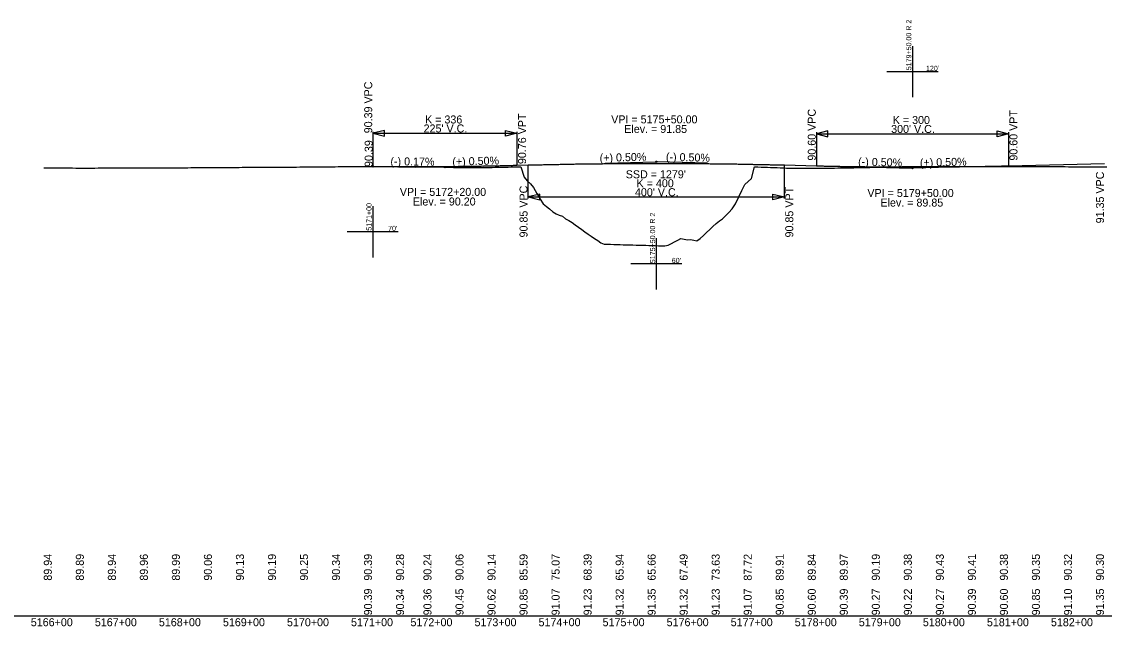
# Model space of a CAD drawing. Extents: x 2147288 to 2220488, y 740833 to 759333.
# Drawn here: x 2148940 to 2150631, y 758067 to 759012 of the extents above; entities that cross this region are included whole.
import ezdxf

# ---------------------------------------------------------------- set-up
doc = ezdxf.new("R2010")
doc.units = 0
for name, color, linetype in [('RD_DDB_GradeTX', 7, 'Continuous'), ('RD_DDB_Profile_EX', 7, 'Continuous'), ('RD_DDB_Profile_Lbl', 7, 'Continuous'), ('RD_DDB_Profile_PR', 7, 'Continuous'), ('RD_DDB_StaTX', 7, 'Continuous'), ('RD_DDB_StripGrade', 7, 'Continuous'), ('RD_DDB_VCLbl', 7, 'Continuous'), ('RD_GPK_Profile_Cell', 7, 'Continuous')]:
    doc.layers.add(name, color=color, linetype=linetype)

msp = doc.modelspace()

# ---------------------------------------------------------------- linework, layer by layer
at = {"layer": 'RD_DDB_GradeTX'}
for p, q in [((2149851.1, 758790.7), (2149930.1, 758792.7)), ((2150011.1, 758790.7), (2149932.1, 758792.7)), ((2149538.3, 758785), (2149600.1, 758784.4)), ((2149681.1, 758786.4), (2149602.1, 758784.5)), ((2150251.1, 758784.7), (2150330.1, 758782.7)), ((2150411.1, 758784.7), (2150332.1, 758782.7))]:
    msp.add_line(p, q, dxfattribs=at)
for centre in [(2149931.1, 758792.7), (2149488.3, 758785.4), (2149601.1, 758784.4), (2150331.1, 758782.7)]:
    msp.add_circle(centre, 1, dxfattribs=at)
at = {"layer": 'RD_DDB_Profile_EX'}
for points in [[(2148974.6, 758783.1), (2148979.6, 758783.1), (2148984.6, 758783.1), (2148989.6, 758783.1), (2148994.6, 758783.2), (2148999.6, 758783.1), (2149004.6, 758783.1), (2149009.6, 758783), (2149014.6, 758783), (2149019.6, 758783), (2149024.6, 758782.9), (2149029.6, 758782.9), (2149034.6, 758782.8), (2149039.6, 758782.9), (2149044.6, 758782.9), (2149049.6, 758782.9), (2149054.6, 758782.9), (2149059.6, 758783), (2149064.6, 758783), (2149069.6, 758783), (2149074.6, 758783), (2149079.6, 758783.1), (2149084.6, 758783.1), (2149089.6, 758783.1), (2149094.6, 758783.2), (2149099.6, 758783.2), (2149104.6, 758783.2), (2149109.6, 758783.2), (2149114.6, 758783.2), (2149119.6, 758783.2), (2149124.6, 758783.2), (2149129.6, 758783.2), (2149134.6, 758783.2), (2149139.6, 758783.2), (2149144.6, 758783.2), (2149149.6, 758783.2), (2149154.6, 758783.2), (2149159.6, 758783.3), (2149164.6, 758783.3), (2149169.6, 758783.3), (2149174.6, 758783.3), (2149179.6, 758783.3), (2149184.6, 758783.3), (2149189.6, 758783.4), (2149194.6, 758783.4), (2149199.6, 758783.4), (2149204.6, 758783.5), (2149209.6, 758783.5), (2149214.6, 758783.5), (2149219.6, 758783.6), (2149224.6, 758783.6), (2149229.6, 758783.6), (2149234.6, 758783.7), (2149239.6, 758783.7), (2149244.6, 758783.8), (2149249.6, 758783.8), (2149254.6, 758783.8), (2149259.6, 758783.9), (2149264.6, 758783.9), (2149269.6, 758784), (2149274.6, 758784), (2149279.6, 758784), (2149284.6, 758784.1), (2149289.6, 758784.1), (2149294.6, 758784.1), (2149299.6, 758784.2), (2149304.6, 758784.2), (2149309.6, 758784.2), (2149314.6, 758784.2), (2149319.6, 758784.3), (2149324.6, 758784.3), (2149329.6, 758784.3), (2149334.6, 758784.3), (2149339.6, 758784.4), (2149344.6, 758784.4), (2149349.6, 758784.4), (2149354.6, 758784.4), (2149359.6, 758784.5), (2149364.6, 758784.5), (2149369.6, 758784.5), (2149374.6, 758784.6), (2149379.6, 758784.6), (2149384.6, 758784.7), (2149389.6, 758784.7), (2149394.6, 758784.7), (2149399.6, 758784.8), (2149404.6, 758784.8), (2149409.6, 758784.9), (2149414.6, 758784.9), (2149419.6, 758784.9), (2149424.6, 758785), (2149429.6, 758785), (2149434.6, 758785.1), (2149439.6, 758785.1), (2149444.6, 758785.2), (2149449.6, 758785.2), (2149454.6, 758785.3), (2149459.6, 758785.3), (2149464.6, 758785.4), (2149469.6, 758785.4), (2149474.6, 758785.5)], [(2149474.6, 758785.5), (2149479.6, 758785.4), (2149484.6, 758785.4), (2149489.6, 758785.4), (2149494.6, 758785.4), (2149499.6, 758785.3), (2149504.6, 758785.3), (2149509.6, 758785.3), (2149514.6, 758785.2), (2149519.6, 758785.1), (2149524.6, 758785.1), (2149529.6, 758785), (2149534.6, 758784.9), (2149538.3, 758784.8)], [(2149538.3, 758784.8), (2149539.6, 758784.8), (2149544.6, 758784.7), (2149549.6, 758784.6), (2149554.6, 758784.5), (2149559.6, 758784.6), (2149564.6, 758784.6), (2149569.6, 758784.6), (2149574.6, 758784.6), (2149579.6, 758784.6), (2149584.6, 758784.6), (2149589.6, 758784.7), (2149594.6, 758784.6), (2149599.6, 758784.4), (2149604.6, 758784.3), (2149609.6, 758784.1), (2149614.6, 758784), (2149619.6, 758783.8), (2149624.6, 758783.8), (2149629.6, 758783.7), (2149634.6, 758783.7), (2149639.6, 758783.7), (2149644.6, 758783.7), (2149649.6, 758783.8), (2149654.6, 758783.8), (2149659.6, 758783.9), (2149664.6, 758783.9), (2149669.6, 758784), (2149674.6, 758784), (2149679.6, 758784.1), (2149684.6, 758784.2), (2149689.6, 758784.3), (2149694.6, 758784.4), (2149699.6, 758784.5), (2149704.6, 758784.6), (2149709.6, 758784.7), (2149714.6, 758784.8), (2149719.6, 758784.8), (2149724.6, 758768.8), (2149729.6, 758762.7), (2149734.6, 758758.3), (2149739.6, 758752.4), (2149744.6, 758742.9), (2149749.6, 758734.1), (2149754.6, 758727.2), (2149759.6, 758723.1), (2149764.6, 758719), (2149769.6, 758714.6), (2149774.6, 758711.4), (2149779.6, 758709.2), (2149784.6, 758707.6), (2149789.6, 758703.4), (2149794.6, 758701), (2149799.6, 758697.7), (2149804.6, 758694.3), (2149809.6, 758690.6), (2149814.6, 758686.9), (2149819.6, 758683.3), (2149824.6, 758679.8), (2149829.6, 758676.4), (2149834.6, 758673), (2149839.6, 758669.6), (2149844.6, 758666.2), (2149849.6, 758664), (2149854.6, 758663.9), (2149859.6, 758663.8), (2149864.6, 758663.6), (2149869.6, 758663.5), (2149874.6, 758663.3), (2149879.6, 758663.2), (2149884.6, 758663), (2149889.6, 758662.9), (2149894.6, 758662.8), (2149899.6, 758662.6), (2149904.6, 758662.5), (2149909.6, 758662.3), (2149914.6, 758662.2), (2149919.6, 758662.1), (2149924.6, 758661.9), (2149929.6, 758661.8), (2149934.6, 758661.6), (2149939.6, 758661.5), (2149944.6, 758661.3), (2149949.6, 758662.3), (2149954.6, 758664.9), (2149959.6, 758667.5), (2149964.6, 758670), (2149969.6, 758672.6), (2149974.6, 758671.8), (2149979.6, 758670.7), (2149984.6, 758671.2), (2149989.6, 758670.1), (2149994.6, 758669), (2149999.6, 758672.8), (2150004.6, 758677.4), (2150009.6, 758682.1), (2150014.6, 758686.7), (2150019.6, 758691.4), (2150024.6, 758696.1), (2150029.6, 758700.7), (2150034.6, 758703.6)], [(2150034.6, 758703.6), (2150039.6, 758708.9), (2150044.6, 758713.5), (2150049.6, 758719.2), (2150054.6, 758726.8), (2150059.6, 758737.1), (2150064.6, 758747.8), (2150069.6, 758757.3), (2150074.6, 758762), (2150079.6, 758766.5), (2150084.6, 758784.9), (2150089.6, 758784.7), (2150094.6, 758784.5), (2150099.6, 758784.3), (2150104.6, 758784.1), (2150109.6, 758783.9), (2150114.6, 758783.7), (2150119.6, 758783.5), (2150124.6, 758783.2), (2150129.6, 758783), (2150134.6, 758782.9), (2150139.6, 758782.9), (2150144.6, 758782.8), (2150149.6, 758782.8), (2150154.6, 758782.8), (2150159.6, 758782.7), (2150164.6, 758782.7), (2150169.6, 758782.7), (2150174.6, 758782.6), (2150179.6, 758782.6), (2150184.6, 758782.6), (2150189.6, 758782.7), (2150194.6, 758782.8), (2150199.6, 758782.8), (2150204.6, 758782.9), (2150209.6, 758782.9), (2150214.6, 758783), (2150219.6, 758783.1), (2150224.6, 758783.2), (2150229.6, 758783.3), (2150234.6, 758783.3), (2150239.6, 758783.4), (2150244.6, 758783.5), (2150249.6, 758783.6), (2150254.6, 758783.7), (2150259.6, 758783.8), (2150264.6, 758783.9), (2150269.6, 758784.1), (2150274.6, 758784.2), (2150279.6, 758784.3), (2150284.6, 758784.4), (2150289.6, 758784.6), (2150294.6, 758784.7), (2150299.6, 758784.8), (2150304.6, 758784.9), (2150309.6, 758785), (2150314.6, 758785.1), (2150319.6, 758785.1), (2150324.6, 758785.2), (2150329.6, 758785.3), (2150334.6, 758785.4), (2150339.6, 758785.4), (2150344.6, 758785.5), (2150349.6, 758785.5), (2150354.6, 758785.5), (2150359.6, 758785.5), (2150364.6, 758785.5), (2150369.6, 758785.5), (2150374.6, 758785.6), (2150379.6, 758785.6), (2150384.6, 758785.6), (2150389.6, 758785.5), (2150394.6, 758785.5), (2150399.6, 758785.5), (2150404.6, 758785.5), (2150409.6, 758785.5), (2150414.6, 758785.5), (2150419.6, 758785.5), (2150424.6, 758785.5), (2150429.6, 758785.5), (2150434.6, 758785.4), (2150439.6, 758785.4), (2150444.6, 758785.4), (2150449.6, 758785.4), (2150454.6, 758785.4), (2150459.6, 758785.4), (2150464.6, 758785.4), (2150469.6, 758785.3), (2150474.6, 758785.3), (2150479.6, 758785.3), (2150484.6, 758785.3), (2150489.6, 758785.3), (2150494.6, 758785.3), (2150499.6, 758785.3), (2150504.6, 758785.3), (2150509.6, 758785.3), (2150514.6, 758785.2), (2150519.6, 758785.2), (2150524.6, 758785.2), (2150529.6, 758785.2), (2150534.6, 758785.2)], [(2150534.6, 758785.2), (2150539.6, 758785.2), (2150544.6, 758785.2), (2150549.6, 758785.1), (2150554.6, 758785.1), (2150559.6, 758785.1), (2150564.6, 758785.1), (2150569.6, 758785.1), (2150574.6, 758785), (2150579.6, 758785), (2150584.6, 758785), (2150589.6, 758785), (2150594.6, 758785), (2150599.6, 758785), (2150604.6, 758785), (2150609.6, 758785), (2150614.6, 758785), (2150619.6, 758785), (2150624.6, 758784.9), (2150629.6, 758784.9), (2150634.6, 758784.9)]]:
    msp.add_lwpolyline(points, dxfattribs=at)
at = {"layer": 'RD_DDB_Profile_PR'}
for p, q in [((2149488.3, 758785.4), (2149488.6, 758785.4)), ((2149713.6, 758787.2), (2149731.1, 758787.7)), ((2150131.1, 758787.7), (2150181.1, 758786.4)), ((2150481.1, 758786.4), (2150631.1, 758790.2))]:
    msp.add_line(p, q, dxfattribs=at)
for points in [[(2149488.6, 758785.4), (2149489.6, 758785.4), (2149490.6, 758785.4), (2149491.6, 758785.4), (2149492.6, 758785.4), (2149493.6, 758785.3), (2149494.5, 758785.3), (2149495.5, 758785.3), (2149496.5, 758785.3), (2149497.5, 758785.3), (2149498.5, 758785.3), (2149499.5, 758785.3), (2149500.5, 758785.3), (2149501.5, 758785.3), (2149502.5, 758785.3), (2149503.5, 758785.3), (2149504.5, 758785.3), (2149505.5, 758785.3), (2149506.5, 758785.3), (2149507.5, 758785.3), (2149508.5, 758785.2), (2149509.5, 758785.2), (2149510.5, 758785.2), (2149511.4, 758785.2), (2149512.4, 758785.2), (2149513.4, 758785.2), (2149514.4, 758785.2), (2149515.4, 758785.2), (2149516.4, 758785.2), (2149517.4, 758785.2), (2149518.4, 758785.2), (2149519.4, 758785.2), (2149520.4, 758785.2), (2149521.4, 758785.2), (2149522.4, 758785.2), (2149523.4, 758785.2), (2149524.4, 758785.2), (2149525.4, 758785.2), (2149526.4, 758785.2), (2149527.4, 758785.2), (2149528.3, 758785.2), (2149529.3, 758785.2), (2149530.3, 758785.2), (2149531.3, 758785.2), (2149532.3, 758785.2), (2149533.3, 758785.2), (2149534.3, 758785.2), (2149535.3, 758785.1), (2149536.3, 758785.1), (2149537.3, 758785.1), (2149538.3, 758785.1)], [(2149538.3, 758785.1), (2149541.8, 758785.1), (2149545.3, 758785.1), (2149548.8, 758785.1), (2149552.3, 758785.1), (2149555.8, 758785.1), (2149559.3, 758785.2), (2149562.8, 758785.2), (2149566.3, 758785.2), (2149569.8, 758785.2), (2149573.3, 758785.2), (2149576.9, 758785.2), (2149580.4, 758785.2), (2149583.9, 758785.3), (2149587.4, 758785.3), (2149590.9, 758785.3), (2149594.4, 758785.3), (2149597.9, 758785.3), (2149601.4, 758785.4), (2149604.9, 758785.4), (2149608.4, 758785.4), (2149611.9, 758785.5), (2149615.4, 758785.5), (2149618.9, 758785.5), (2149622.4, 758785.6), (2149625.9, 758785.6), (2149629.4, 758785.7), (2149632.9, 758785.7), (2149636.5, 758785.8), (2149640, 758785.8), (2149643.5, 758785.9), (2149647, 758785.9), (2149650.5, 758786), (2149654, 758786), (2149657.5, 758786.1), (2149661, 758786.1), (2149664.5, 758786.2), (2149668, 758786.3), (2149671.5, 758786.3), (2149675, 758786.4), (2149678.5, 758786.5), (2149682, 758786.5), (2149685.5, 758786.6), (2149689, 758786.7), (2149692.5, 758786.7), (2149696.1, 758786.8), (2149699.6, 758786.9), (2149703.1, 758787), (2149706.6, 758787.1), (2149710.1, 758787.2), (2149713.6, 758787.2)], [(2149731.1, 758787.7), (2149739.1, 758787.9), (2149747.1, 758788.1), (2149755.1, 758788.2), (2149763.1, 758788.4), (2149771.1, 758788.6), (2149779.1, 758788.7), (2149787.1, 758788.9), (2149795.1, 758789), (2149803.1, 758789.2), (2149811.1, 758789.3), (2149819.1, 758789.4), (2149827.1, 758789.5), (2149835.1, 758789.6), (2149843.1, 758789.7), (2149851.1, 758789.8), (2149859.1, 758789.9), (2149867.1, 758789.9), (2149875.1, 758790), (2149883.1, 758790), (2149891.1, 758790.1), (2149899.1, 758790.1), (2149907.1, 758790.1), (2149915.1, 758790.2), (2149923.1, 758790.2), (2149931.1, 758790.2), (2149939.1, 758790.2), (2149947.1, 758790.2), (2149955.1, 758790.1), (2149963.1, 758790.1), (2149971.1, 758790.1), (2149979.1, 758790), (2149987.1, 758790), (2149995.1, 758789.9), (2150003.1, 758789.9), (2150011.1, 758789.8), (2150019.1, 758789.7), (2150027.1, 758789.6), (2150035.1, 758789.5), (2150043.1, 758789.4), (2150051.1, 758789.3), (2150059.1, 758789.2), (2150067.1, 758789), (2150075.1, 758788.9), (2150083.1, 758788.7), (2150091.1, 758788.6), (2150099.1, 758788.4), (2150107.1, 758788.2), (2150115.1, 758788.1), (2150123.1, 758787.9), (2150131.1, 758787.7)], [(2150181.1, 758786.4), (2150187.1, 758786.3), (2150193.1, 758786.1), (2150199.1, 758786), (2150205.1, 758785.9), (2150211.1, 758785.8), (2150217.1, 758785.6), (2150223.1, 758785.5), (2150229.1, 758785.4), (2150235.1, 758785.3), (2150241.1, 758785.2), (2150247.1, 758785.1), (2150253.1, 758785.1), (2150259.1, 758785), (2150265.1, 758784.9), (2150271.1, 758784.9), (2150277.1, 758784.8), (2150283.1, 758784.7), (2150289.1, 758784.7), (2150295.1, 758784.7), (2150301.1, 758784.6), (2150307.1, 758784.6), (2150313.1, 758784.6), (2150319.1, 758784.6), (2150325.1, 758784.6), (2150331.1, 758784.6), (2150337.1, 758784.6), (2150343.1, 758784.6), (2150349.1, 758784.6), (2150355.1, 758784.6), (2150361.1, 758784.6), (2150367.1, 758784.7), (2150373.1, 758784.7), (2150379.1, 758784.7), (2150385.1, 758784.8), (2150391.1, 758784.9), (2150397.1, 758784.9), (2150403.1, 758785), (2150409.1, 758785.1), (2150415.1, 758785.1), (2150421.1, 758785.2), (2150427.1, 758785.3), (2150433.1, 758785.4), (2150439.1, 758785.5), (2150445.1, 758785.6), (2150451.1, 758785.8), (2150457.1, 758785.9), (2150463.1, 758786), (2150469.1, 758786.1), (2150475.1, 758786.3), (2150481.1, 758786.4)]]:
    msp.add_spline(points, degree=3, dxfattribs=at)
at = {"layer": 'RD_DDB_VCLbl'}
for p, q in [((2149488.6, 758839.7), (2149488.6, 758785.4)), ((2149488.6, 758837.2), (2149538.3, 758837.2)), ((2149538.3, 758837.2), (2149713.6, 758837.2)), ((2149713.6, 758839.7), (2149713.6, 758787.2)), ((2150181.1, 758838.9), (2150181.1, 758786.4)), ((2150181.1, 758836.4), (2150481.1, 758836.4)), ((2150481.1, 758838.9), (2150481.1, 758786.4)), ((2149731.1, 758735.2), (2149731.1, 758787.7)), ((2150131.1, 758735.2), (2150131.1, 758787.7)), ((2149731.1, 758737.7), (2150131.1, 758737.7))]:
    msp.add_line(p, q, dxfattribs=at)
for points in [[(2149506.6, 758841.7), (2149488.6, 758837.2), (2149506.6, 758832.7)], [(2149695.6, 758841.7), (2149713.6, 758837.2), (2149695.6, 758832.7)], [(2150199.1, 758840.9), (2150181.1, 758836.4), (2150199.1, 758831.9)], [(2150463.1, 758840.9), (2150481.1, 758836.4), (2150463.1, 758831.9)], [(2149749.1, 758742.2), (2149731.1, 758737.7), (2149749.1, 758733.2)], [(2150113.1, 758742.2), (2150131.1, 758737.7), (2150113.1, 758733.2)]]:
    msp.add_lwpolyline(points, close=True, dxfattribs=at)
at = {"layer": 'RD_GPK_Profile_Cell'}
for p, q in [((2150331.1, 758973.4), (2150331.1, 758893.4)), ((2150371.1, 758933.4), (2150291.1, 758933.4)), ((2149488.3, 758723.4), (2149488.3, 758643.4)), ((2149528.3, 758683.4), (2149448.3, 758683.4)), ((2149931.1, 758673.4), (2149931.1, 758593.4)), ((2149971.1, 758633.4), (2149891.1, 758633.4)), ((2148888.3, 758083.4), (2165888.3, 758083.4))]:
    msp.add_line(p, q, dxfattribs=at)

# ---------------------------------------------------------------- texts
at = {"layer": 'RD_DDB_GradeTX'}
for s, rotation, p in [('(-) 0.17%', 359.512, (2149516, 758787.2)), ('(+) 0.50%', 1.4321, (2149612.8, 758786.7)), ('(+) 0.50%', 1.4321, (2149842.8, 758792.5)), ('(-) 0.50%', 358.5679, (2149946, 758794.3)), ('(-) 0.50%', 358.5679, (2150246.1, 758786.8)), ('(+) 0.50%', 1.4321, (2150342.8, 758785))]:
    msp.add_text(s, height=12.5, rotation=rotation, dxfattribs=at).set_placement(p)
at = {"layer": 'RD_DDB_Profile_Lbl'}
for s, p in [('VPI = 5175+50.00', (2149860.7, 758852.7)), ('Elev. = 91.85', (2149881.1, 758837.7)), ('VPI = 5172+20.00', (2149530.7, 758739.4)), ('VPI = 5179+50.00', (2150260.7, 758737.7)), ('Elev. = 90.20', (2149551, 758724.4)), ('Elev. = 89.85', (2150281.1, 758722.7))]:
    msp.add_text(s, height=12.5, dxfattribs=at).set_placement(p)
msp.add_text('90.39', height=12.5, rotation=90, dxfattribs=at).set_placement((2149488.3, 758784.6))
at = {"layer": 'RD_DDB_StaTX'}
for s, p in [('5166+00', (2148954.5, 758067.2)), ('5167+00', (2149054.5, 758067.2)), ('5168+00', (2149154.5, 758067.2)), ('5169+00', (2149254.5, 758067.2)), ('5170+00', (2149354.5, 758067.2)), ('5171+00', (2149454.5, 758067.2)), ('5172+00', (2149547.3, 758067.2)), ('5173+00', (2149647.3, 758067.2)), ('5174+00', (2149747.3, 758067.2)), ('5175+00', (2149847.3, 758067.2)), ('5176+00', (2149947.3, 758067.2)), ('5177+00', (2150047.3, 758067.2)), ('5178+00', (2150147.3, 758067.2)), ('5179+00', (2150247.3, 758067.2)), ('5180+00', (2150347.3, 758067.2)), ('5181+00', (2150447.3, 758067.2)), ('5182+00', (2150547.3, 758067.2))]:
    msp.add_text(s, height=12.5, dxfattribs=at).set_placement(p)
at = {"layer": 'RD_DDB_StripGrade'}
for s, p in [('90.39 VPC', (2149487.6, 758837.2)), ('90.76 VPT', (2149727.8, 758789.1)), ('90.60 VPC', (2150180.1, 758794.5)), ('90.60 VPT', (2150495, 758794.5)), ('91.35 VPC', (2150630.1, 758696.5)), ('90.85 VPC', (2149730.1, 758674.5)), ('90.85 VPT', (2150145, 758674.5)), ('89.94', (2148987.3, 758138.4)), ('89.89', (2149037.3, 758138.4)), ('89.94', (2149087.3, 758138.4)), ('89.96', (2149137.3, 758138.4)), ('89.99', (2149187.3, 758138.4)), ('90.06', (2149237.3, 758138.4)), ('90.13', (2149287.3, 758138.4)), ('90.19', (2149337.3, 758138.4)), ('90.25', (2149387.3, 758138.4)), ('90.34', (2149437.3, 758138.4)), ('90.39', (2149487.3, 758138.4)), ('90.28', (2149537.3, 758138.4)), ('90.24', (2149580.1, 758138.4)), ('90.06', (2149630.1, 758138.4)), ('90.14', (2149680.1, 758138.4)), ('85.59', (2149730.1, 758138.4)), ('75.07', (2149780.1, 758138.4)), ('68.39', (2149830.1, 758138.4)), ('65.94', (2149880.1, 758138.4)), ('65.66', (2149930.1, 758138.4)), ('67.49', (2149980.1, 758138.4)), ('73.63', (2150030.1, 758138.4)), ('87.72', (2150080.1, 758138.4)), ('89.91', (2150130.1, 758138.4)), ('89.84', (2150180.1, 758138.4)), ('89.97', (2150230.1, 758138.4)), ('90.19', (2150280.1, 758138.4)), ('90.38', (2150330.1, 758138.4)), ('90.43', (2150380.1, 758138.4)), ('90.41', (2150430.1, 758138.4)), ('90.38', (2150480.1, 758138.4)), ('90.35', (2150530.1, 758138.4)), ('90.32', (2150580.1, 758138.4)), ('90.30', (2150630.1, 758138.4)), ('90.39', (2149487.3, 758084.2)), ('90.34', (2149537.3, 758084.2)), ('90.36', (2149580.1, 758084.2)), ('90.45', (2149630.1, 758084.2)), ('90.62', (2149680.1, 758084.2)), ('90.85', (2149730.1, 758084.2)), ('91.07', (2149780.1, 758084.2)), ('91.23', (2149830.1, 758084.2)), ('91.32', (2149880.1, 758084.2)), ('91.35', (2149930.1, 758084.2)), ('91.32', (2149980.1, 758084.2)), ('91.23', (2150030.1, 758084.2)), ('91.07', (2150080.1, 758084.2)), ('90.85', (2150130.1, 758084.2)), ('90.60', (2150180.1, 758084.2)), ('90.39', (2150230.1, 758084.2)), ('90.27', (2150280.1, 758084.2)), ('90.22', (2150330.1, 758084.2)), ('90.27', (2150380.1, 758084.2)), ('90.39', (2150430.1, 758084.2)), ('90.60', (2150480.1, 758084.2)), ('90.85', (2150530.1, 758084.2)), ('91.10', (2150580.1, 758084.2)), ('91.35', (2150630.1, 758084.2))]:
    msp.add_text(s, height=12.5, rotation=90, dxfattribs=at).set_placement(p)
at = {"layer": 'RD_DDB_VCLbl'}
for s, p in [('K = 336', (2149570.1, 758852.5)), ('K = 300', (2150300.3, 758851.7)), ("225' V.C.", (2149567.8, 758838.5)), ("300' V.C.", (2150297.8, 758837.7)), ("SSD = 1279'", (2149883.4, 758766.9)), ('K = 400', (2149900.3, 758752.9)), ("400' V.C.", (2149897.8, 758738.9))]:
    msp.add_text(s, height=12.5, dxfattribs=at).set_placement(p)
at = {"layer": 'RD_GPK_Profile_Cell'}
for s, p in [('5179+50.00 R 2', (2150329.3, 758935.7)), ('5171+00', (2149486.5, 758685)), ('5175+50.00 R 2', (2149929.3, 758634.3))]:
    msp.add_text(s, height=8, rotation=90, dxfattribs=at).set_placement(p)
for s, p in [("120'", (2150352.2, 758934.6)), ("70'", (2149512.4, 758684.6)), ("60'", (2149955.2, 758634.6))]:
    msp.add_text(s, height=8, dxfattribs=at).set_placement(p)

doc.saveas('drawing.dxf')
